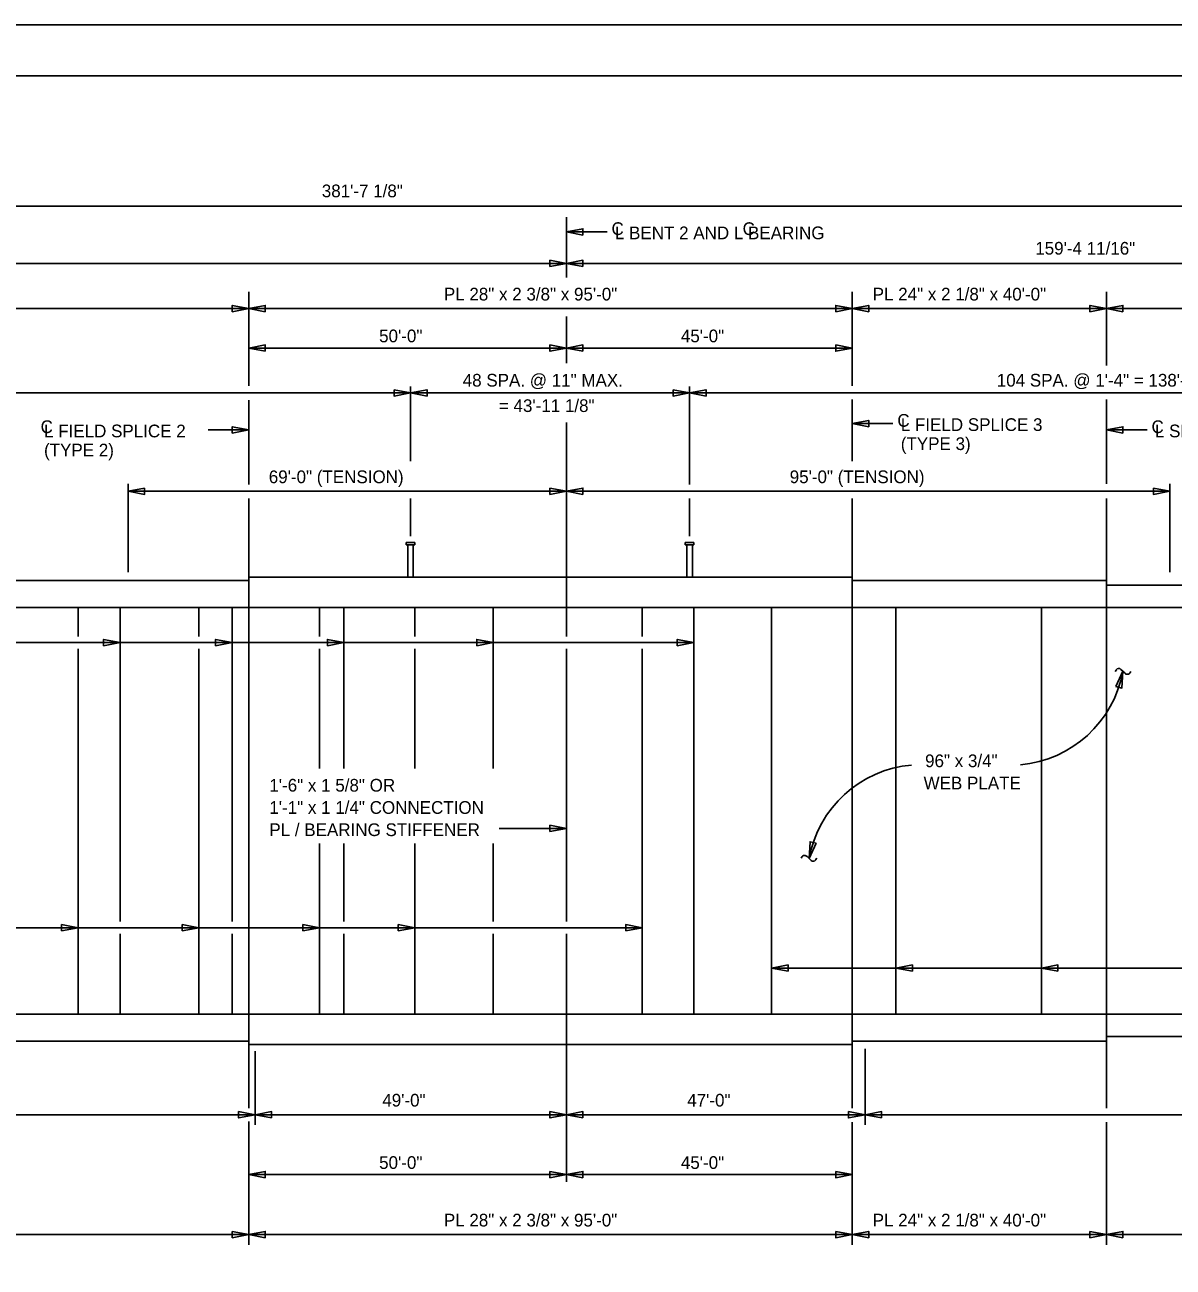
# Model space of a CAD drawing. Extents: x -305 to -161, y -187 to -99.
# Drawn here: x -249.19 to -204.01, y -148.37 to -99.49 of the extents above; entities that cross this region are included whole.
import ezdxf

# ---------------------------------------------------------------- set-up
doc = ezdxf.new("R2010")
doc.units = 0
for name, color, linetype in [('BR_AUTO DIMENSION', 7, 'Continuous'), ('BR_BORDER LINES', 7, 'Continuous'), ('BR_CENTER LINES', 7, 'Continuous'), ('BR_STRUCTURAL STEEL', 7, 'Continuous'), ('BR_TEXT', 7, 'Continuous'), ('Default', 7, 'Continuous'), ('Level 31', 7, 'Continuous')]:
    doc.layers.add(name, color=color, linetype=linetype)

msp = doc.modelspace()

# ---------------------------------------------------------------- linework, layer by layer
at = {"layer": 'BR_AUTO DIMENSION'}
for p, q in [((-284.433, -106.618), (-187.347, -106.618)), ((-227.882, -107.634), (-226.283, -107.634)), ((-284.433, -108.876), (-227.882, -108.876)), ((-227.882, -108.876), (-187.347, -108.876)), ((-240.382, -110.653), (-269.132, -110.653)), ((-240.382, -110.653), (-216.632, -110.653)), ((-216.632, -110.653), (-206.632, -110.653)), ((-187.347, -110.653), (-206.632, -110.653)), ((-227.882, -112.204), (-240.382, -112.204)), ((-216.652, -112.204), (-227.902, -112.204)), ((-234.016, -116.66), (-234.016, -113.721)), ((-223.034, -117.567), (-223.034, -113.721)), ((-282.766, -113.971), (-234.016, -113.971)), ((-234.016, -113.971), (-223.034, -113.971)), ((-223.034, -113.971), (-188.68, -113.971)), ((-216.632, -115.178), (-215.033, -115.178)), ((-240.382, -115.428), (-241.98, -115.428)), ((-206.632, -115.428), (-205.033, -115.428)), ((-245.132, -117.55), (-245.132, -121.025)), ((-204.132, -117.55), (-204.132, -121.025)), ((-245.132, -117.84), (-227.882, -117.84)), ((-234.016, -119.6), (-234.016, -118.13)), ((-204.132, -117.84), (-227.882, -117.84)), ((-223.034, -119.6), (-223.034, -118.13)), ((-222.868, -123.792), (-287.791, -123.792)), ((-227.882, -131.107), (-230.53, -131.107)), ((-224.9, -135.013), (-287.791, -135.013)), ((-219.809, -136.601), (-183.797, -136.601)), ((-216.132, -139.78), (-216.132, -142.773)), ((-240.132, -139.874), (-240.132, -142.773)), ((-240.132, -142.367), (-284.433, -142.367)), ((-227.882, -142.367), (-240.132, -142.367)), ((-216.132, -142.367), (-227.882, -142.367)), ((-187.347, -142.367), (-216.132, -142.367)), ((-227.882, -144.726), (-240.382, -144.726)), ((-216.632, -144.726), (-227.882, -144.726)), ((-269.132, -147.085), (-240.382, -147.085)), ((-240.382, -147.085), (-216.632, -147.085)), ((-216.632, -147.085), (-206.632, -147.085)), ((-206.632, -147.085), (-187.347, -147.085))]:
    msp.add_line(p, q, dxfattribs=at)
for points in [[(-227.232, -107.759), (-227.882, -107.634), (-227.232, -107.509)], [(-228.532, -109.001), (-227.882, -108.876), (-228.532, -108.751)], [(-227.232, -109.001), (-227.882, -108.876), (-227.232, -108.751)], [(-241.032, -110.778), (-240.382, -110.653), (-241.032, -110.528)], [(-239.732, -110.778), (-240.382, -110.653), (-239.732, -110.528)], [(-217.282, -110.778), (-216.632, -110.653), (-217.282, -110.528)], [(-215.982, -110.778), (-216.632, -110.653), (-215.982, -110.528)], [(-207.282, -110.778), (-206.632, -110.653), (-207.282, -110.528)], [(-205.982, -110.778), (-206.632, -110.653), (-205.982, -110.528)], [(-239.732, -112.329), (-240.382, -112.204), (-239.732, -112.079)], [(-228.532, -112.079), (-227.882, -112.204), (-228.532, -112.329)], [(-227.232, -112.329), (-227.882, -112.204), (-227.232, -112.079)], [(-217.282, -112.079), (-216.632, -112.204), (-217.282, -112.329)], [(-234.666, -113.846), (-234.016, -113.971), (-234.666, -114.096)], [(-233.366, -114.096), (-234.016, -113.971), (-233.366, -113.846)], [(-223.684, -113.846), (-223.034, -113.971), (-223.684, -114.096)], [(-222.384, -114.096), (-223.034, -113.971), (-222.384, -113.846)], [(-241.032, -115.553), (-240.382, -115.428), (-241.032, -115.303)], [(-215.982, -115.303), (-216.632, -115.178), (-215.982, -115.053)], [(-205.982, -115.553), (-206.632, -115.428), (-205.982, -115.303)], [(-244.482, -117.715), (-245.132, -117.84), (-244.482, -117.965)], [(-228.532, -117.715), (-227.882, -117.84), (-228.532, -117.965)], [(-227.232, -117.965), (-227.882, -117.84), (-227.232, -117.715)], [(-204.782, -117.715), (-204.132, -117.84), (-204.782, -117.965)], [(-246.095, -123.917), (-245.445, -123.792), (-246.095, -123.667)], [(-241.691, -123.917), (-241.041, -123.792), (-241.691, -123.667)], [(-237.286, -123.917), (-236.636, -123.792), (-237.286, -123.667)], [(-231.414, -123.917), (-230.764, -123.792), (-231.414, -123.667)], [(-223.518, -123.917), (-222.868, -123.792), (-223.518, -123.667)], [(-206.265, -125.52), (-205.982, -124.922), (-206.023, -125.582)], [(-228.532, -131.232), (-227.882, -131.107), (-228.532, -130.982)], [(-218.051, -131.689), (-218.334, -132.287), (-218.293, -131.627)], [(-247.749, -135.138), (-247.099, -135.013), (-247.749, -134.888)], [(-242.999, -135.138), (-242.349, -135.013), (-242.999, -134.888)], [(-238.249, -135.138), (-237.599, -135.013), (-238.249, -134.888)], [(-234.499, -135.138), (-233.849, -135.013), (-234.499, -134.888)], [(-225.55, -135.138), (-224.9, -135.013), (-225.55, -134.888)], [(-219.159, -136.726), (-219.809, -136.601), (-219.159, -136.476)], [(-214.268, -136.726), (-214.918, -136.601), (-214.268, -136.476)], [(-208.54, -136.726), (-209.19, -136.601), (-208.54, -136.476)], [(-240.782, -142.242), (-240.132, -142.367), (-240.782, -142.492)], [(-239.482, -142.492), (-240.132, -142.367), (-239.482, -142.242)], [(-228.532, -142.242), (-227.882, -142.367), (-228.532, -142.492)], [(-227.232, -142.492), (-227.882, -142.367), (-227.232, -142.242)], [(-216.782, -142.242), (-216.132, -142.367), (-216.782, -142.492)], [(-215.482, -142.492), (-216.132, -142.367), (-215.482, -142.242)], [(-239.732, -144.851), (-240.382, -144.726), (-239.732, -144.601)], [(-228.532, -144.601), (-227.882, -144.726), (-228.532, -144.851)], [(-227.232, -144.851), (-227.882, -144.726), (-227.232, -144.601)], [(-217.282, -144.601), (-216.632, -144.726), (-217.282, -144.851)], [(-241.032, -146.96), (-240.382, -147.085), (-241.032, -147.21)], [(-239.732, -147.21), (-240.382, -147.085), (-239.732, -146.96)], [(-217.282, -146.96), (-216.632, -147.085), (-217.282, -147.21)], [(-215.982, -147.21), (-216.632, -147.085), (-215.982, -146.96)], [(-207.282, -146.96), (-206.632, -147.085), (-207.282, -147.21)], [(-205.982, -147.21), (-206.632, -147.085), (-205.982, -146.96)]]:
    msp.add_lwpolyline(points, close=True, dxfattribs=at)
for centre, start, end in [((-210.407, -124.118), 274.9624, 349.7037), ((-213.909, -133.091), 94.9624, 169.7037)]:
    msp.add_arc(centre, 4.497, start, end, dxfattribs=at)
at = {"layer": 'BR_BORDER LINES'}
msp.add_line((-163.178, -101.489), (-297.843, -101.489), dxfattribs=at)
at = {"layer": 'BR_CENTER LINES'}
for p, q in [((-227.882, -107.059), (-227.882, -109.43)), ((-240.382, -109.997), (-240.382, -113.69)), ((-216.632, -109.997), (-216.632, -113.69)), ((-206.632, -109.997), (-206.632, -112.898)), ((-227.882, -110.967), (-227.882, -112.806)), ((-240.382, -114.253), (-240.382, -117.567)), ((-216.632, -114.23), (-216.632, -116.66)), ((-206.632, -114.23), (-206.632, -117.548)), ((-227.882, -115.136), (-227.882, -122.412)), ((-240.382, -118.13), (-240.382, -124.614)), ((-216.632, -118.13), (-216.632, -142.11)), ((-206.632, -118.13), (-206.632, -142.108)), ((-240.382, -124.614), (-240.382, -142.116)), ((-227.882, -138.412), (-227.882, -145.014)), ((-240.382, -142.631), (-240.382, -147.486)), ((-216.632, -142.664), (-216.632, -147.486)), ((-206.632, -142.667), (-206.632, -147.486))]:
    msp.add_line(p, q, dxfattribs=at)
at = {"layer": 'BR_STRUCTURAL STEEL'}
for p, q in [((-269.132, -121.35), (-240.382, -121.35)), ((-240.382, -122.412), (-240.382, -121.225)), ((-240.382, -121.225), (-216.632, -121.225)), ((-216.632, -121.225), (-216.632, -122.412)), ((-216.632, -121.35), (-206.632, -121.35)), ((-206.632, -121.35), (-206.632, -122.412)), ((-187.347, -121.537), (-206.632, -121.537)), ((-187.347, -122.412), (-284.433, -122.412)), ((-247.099, -122.412), (-247.099, -123.55)), ((-245.445, -122.412), (-245.445, -134.771)), ((-242.349, -122.412), (-242.349, -123.55)), ((-241.041, -122.412), (-241.041, -134.771)), ((-237.599, -122.412), (-237.599, -123.55)), ((-236.636, -122.412), (-236.636, -128.753)), ((-233.849, -122.412), (-233.849, -123.55)), ((-230.764, -122.412), (-230.764, -128.753)), ((-227.882, -122.412), (-227.882, -123.55)), ((-224.9, -123.55), (-224.9, -122.412)), ((-222.868, -138.412), (-222.868, -122.412)), ((-219.809, -138.412), (-219.809, -122.412)), ((-214.918, -138.412), (-214.918, -122.412)), ((-209.19, -138.412), (-209.19, -122.412)), ((-247.099, -124.034), (-247.099, -138.412)), ((-242.349, -124.034), (-242.349, -138.412)), ((-237.599, -124.034), (-237.599, -128.753)), ((-233.849, -124.034), (-233.849, -128.753)), ((-227.882, -124.034), (-227.882, -134.771)), ((-224.9, -138.412), (-224.9, -124.034)), ((-237.599, -131.7), (-237.599, -138.412)), ((-236.636, -131.7), (-236.636, -134.771)), ((-233.849, -131.7), (-233.849, -138.412)), ((-230.764, -131.7), (-230.764, -134.771)), ((-245.445, -135.255), (-245.445, -138.412)), ((-241.041, -135.255), (-241.041, -138.412)), ((-236.636, -135.255), (-236.636, -138.412)), ((-230.764, -135.255), (-230.764, -138.412)), ((-227.882, -135.255), (-227.882, -138.412)), ((-187.347, -138.412), (-284.433, -138.412)), ((-240.382, -138.412), (-240.382, -139.6)), ((-216.632, -139.6), (-216.632, -138.412)), ((-206.632, -139.475), (-206.632, -138.412)), ((-187.347, -139.287), (-206.632, -139.287)), ((-269.132, -139.475), (-240.382, -139.475)), ((-240.382, -139.6), (-216.632, -139.6)), ((-216.632, -139.475), (-206.632, -139.475))]:
    msp.add_line(p, q, dxfattribs=at)
at = {"layer": 'BR_TEXT'}
for p, q in [((-206.242, -124.869), (-206.285, -124.93)), ((-205.901, -124.996), (-206.064, -124.847)), ((-205.668, -124.93), (-205.697, -124.976)), ((-218.648, -132.279), (-218.619, -132.233)), ((-218.415, -132.213), (-218.252, -132.362)), ((-218.074, -132.34), (-218.031, -132.279))]:
    msp.add_line(p, q, dxfattribs=at)
for centre, radius, start, end in [((-206.145, -124.922), 0.111, 43.4519, 151.7375), ((-205.807, -124.915), 0.125, 221.007, 330.8059), ((-218.509, -132.294), 0.125, 41.007, 150.8059), ((-218.171, -132.287), 0.111, 223.4519, 331.7375)]:
    msp.add_arc(centre, radius, start, end, dxfattribs=at)
at = {"layer": 'Default'}
for p, q in [((-234.188, -119.85), (-234.188, -119.944)), ((-234.188, -119.85), (-233.844, -119.85)), ((-234.188, -119.944), (-233.844, -119.944)), ((-234.125, -119.944), (-234.125, -121.225)), ((-233.907, -119.944), (-233.907, -121.225)), ((-233.844, -119.85), (-233.844, -119.944)), ((-223.206, -119.85), (-223.206, -119.944)), ((-223.206, -119.85), (-222.863, -119.85)), ((-223.206, -119.944), (-222.863, -119.944)), ((-223.144, -119.944), (-223.144, -121.225)), ((-222.925, -119.944), (-222.925, -121.225)), ((-222.863, -119.85), (-222.863, -119.944))]:
    msp.add_line(p, q, dxfattribs=at)
at = {"layer": 'Level 31'}
msp.add_lwpolyline([(-305.176, -187.489), (-161.176, -187.489), (-161.176, -99.489), (-305.176, -99.489)], close=True, dxfattribs=at)

# ---------------------------------------------------------------- texts
at = {"layer": 'BR_AUTO DIMENSION'}
for s, p in [('381\'-7 1/8"', (-237.509, -106.272)), ('159\'-4 11/16"', (-209.432, -108.53)), ('PL 28" x 2 3/8" x 95\'-0"', (-232.705, -110.334)), ('PL 24" x 2 1/8" x 40\'-0"', (-215.83, -110.334)), ('50\'-0"', (-235.253, -111.979)), ('45\'-0"', (-223.378, -111.979)), (' 95\'-0" (TENSION)', (-219.281, -117.521)), ('96" x 3/4" ', (-213.768, -128.694)), ('WEB PLATE', (-213.826, -129.569)), ('49\'-0"', (-235.128, -142.048)), ('50\'-0"', (-235.253, -144.501)), ('45\'-0"', (-223.378, -144.501)), ('PL 28" x 2 3/8" x 95\'-0"', (-232.705, -146.766)), ('PL 24" x 2 1/8" x 40\'-0"', (-215.83, -146.766))]:
    msp.add_text(s, height=0.5, rotation=360, dxfattribs=at).set_placement(p)
for s, p in [('48 SPA. @ 11" MAX.', (-231.963, -113.721)), ('104 SPA. @ 1\'-4" = 138\'-8"', (-210.947, -113.721)), ('= 43\'-11 1/8"', (-230.541, -114.721)), (' 69\'-0" (TENSION)', (-239.781, -117.521)), ('47\'-0"', (-223.128, -142.048))]:
    msp.add_text(s, height=0.5, dxfattribs=at).set_placement(p)
at = {"layer": 'BR_TEXT'}
for s, p in [('C', (-226.109, -107.758)), ('L BENT 2 AND L BEARING', (-225.974, -107.924)), ('C', (-220.949, -107.758)), ('C', (-214.859, -115.301)), ('C', (-248.574, -115.551)), ('L FIELD SPLICE 2', (-248.439, -115.718)), ('L FIELD SPLICE 3', (-214.724, -115.468)), ('C', (-204.859, -115.551)), ('L SHOP SPLICE 1', (-204.724, -115.718)), ('(TYPE 3)', (-214.724, -116.218)), ('(TYPE 2)', (-248.439, -116.468)), ('1\'-6" x 1 5/8" OR', (-239.572, -129.656)), ('1\'-1" x 1 1/4" CONNECTION ', (-239.572, -130.531)), ('PL / BEARING STIFFENER', (-239.572, -131.406))]:
    msp.add_text(s, height=0.5, rotation=360, dxfattribs=at).set_placement(p)

doc.saveas('drawing.dxf')
